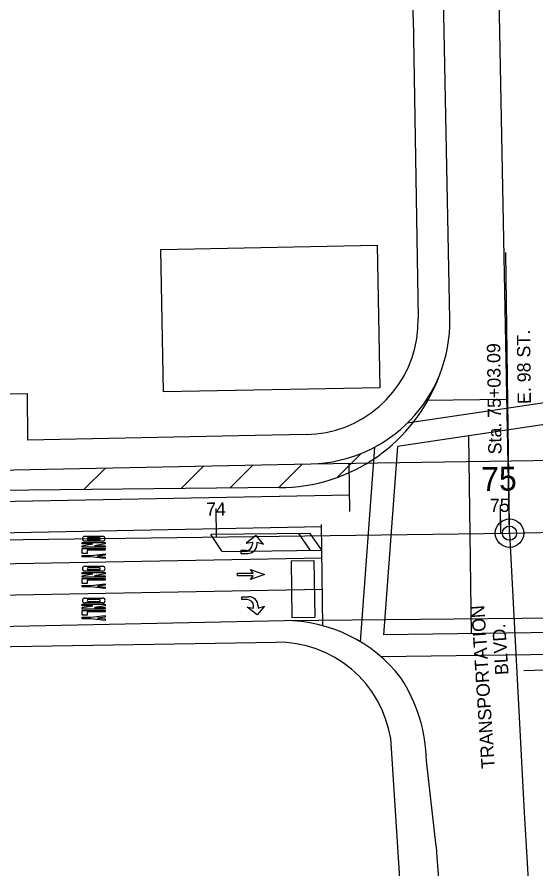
# Model space of a CAD drawing. Extents: x -2233 to 187241, y 4582 to 150524.
# Drawn here: x 107272.9 to 107455.5, y 59338.1 to 59637.9 of the extents above; entities that cross this region are included whole.
import ezdxf

# ---------------------------------------------------------------- set-up
doc = ezdxf.new("R2010")
doc.units = 0
for name, color, linetype in [('BLDG', 7, 'Continuous'), ('GE_X_CL_100', 7, 'Continuous'), ('GE_X_CL_20', 7, 'Continuous'), ('GE_X_CL_2000', 7, 'Continuous'), ('GE_X_CL_50', 7, 'Continuous'), ('PM_P_Cells', 7, 'Continuous'), ('PM_P_Channelizing_Line', 7, 'Continuous'), ('PM_P_CL_Double_Solid', 7, 'Continuous'), ('PM_P_Crosswalk', 7, 'Continuous'), ('PM_P_Dotted_Line', 7, 'Continuous'), ('PM_P_Edge_Line', 7, 'Continuous'), ('PM_P_Stop_Line', 7, 'Continuous'), ('PM_P_Text', 7, 'Continuous'), ('PM_P_Transverse_Line', 7, 'Continuous'), ('ROAD', 7, 'Continuous'), ('RW_X_Fee_RW', 7, 'Continuous'), ('SG_P_Detection', 7, 'Continuous')]:
    doc.layers.add(name, color=color, linetype=linetype)

msp = doc.modelspace()

# ---------------------------------------------------------------- linework, layer by layer
at = {"layer": 'BLDG'}
msp.add_lwpolyline([(107400.52, 59507.44), (107324.44, 59505.98), (107323.49, 59556.17), (107399.57, 59557.62)], close=True, dxfattribs=at)
at = {"layer": 'GE_X_CL_100'}
for p, q in [((107343.14, 59454.91), (107343.01, 59464.91)), ((107443.13, 59456.21), (107443, 59466.21))]:
    msp.add_line(p, q, dxfattribs=at)
msp.add_circle((107446.21, 59456.25), 5, dxfattribs=at)
at = {"layer": 'GE_X_CL_20'}
for p, q in [((107446.21, 59456.25), (107440.88, 59729.76)), ((107446.21, 59456.25), (107777.4, 59464.42)), ((106987.56, 59450.3), (107446.21, 59456.25))]:
    msp.add_line(p, q, dxfattribs=at)
at = {"layer": 'GE_X_CL_2000'}
for p, q in [((107446.21, 59456.25), (107777.4, 59464.42)), ((106987.56, 59450.3), (107446.21, 59456.25))]:
    msp.add_line(p, q, dxfattribs=at)
msp.add_lwpolyline([(107446.21, 59456.25), (107451.38, 59357.9), (107456.65, 59268.72), (107462.78, 59175.01), (107473.27, 58996.9), (107481.81, 58861.26)], dxfattribs=at)
at = {"layer": 'GE_X_CL_50'}
for p, q in [((107446.18, 59458.75), (107444.93, 59555.03)), ((107443.13, 59456.21), (107443.06, 59461.21)), ((107343.14, 59454.91), (107343.07, 59459.91))]:
    msp.add_line(p, q, dxfattribs=at)
msp.add_circle((107446.21, 59456.25), 2.5, dxfattribs=at)
at = {"layer": 'PM_P_Cells'}
for p, q in [((107296.71, 59455.15), (107297.87, 59455.15)), ((107297.87, 59455.15), (107297.87, 59454.65)), ((107297.87, 59454.65), (107297.87, 59455.15)), ((107297.87, 59455.15), (107301.87, 59455.15)), ((107301.87, 59454.65), (107297.87, 59454.65)), ((107301.87, 59454.65), (107301.87, 59455.15)), ((107301.87, 59455.15), (107303.04, 59455.15)), ((107301.87, 59455.15), (107301.87, 59454.65)), ((107357.04, 59455.44), (107353.52, 59452.77)), ((107359.6, 59452.44), (107357.04, 59455.44)), ((107295.87, 59452.48), (107295.87, 59452.98)), ((107295.87, 59452.98), (107303.87, 59452.98)), ((107295.87, 59451.81), (107299.62, 59452.48)), ((107299.62, 59452.48), (107295.87, 59452.48)), ((107295.87, 59451.31), (107295.87, 59451.81)), ((107303.04, 59453.48), (107296.71, 59453.48)), ((107297.87, 59453.98), (107301.87, 59453.98)), ((107303.87, 59452.48), (107300.12, 59451.81)), ((107300.12, 59451.81), (107303.87, 59451.81)), ((107303.87, 59452.98), (107303.87, 59452.48)), ((107303.87, 59451.81), (107303.87, 59451.31)), ((107351.6, 59452.44), (107351.6, 59452.44)), ((107353.52, 59452.77), (107355.76, 59453.1)), ((107355.76, 59453.1), (107355.76, 59452.4)), ((107357.36, 59452.44), (107357.36, 59453.1)), ((107357.36, 59453.1), (107359.6, 59452.44)), ((107359.6, 59452.44), (107359.6, 59452.44)), ((107303.87, 59451.31), (107295.87, 59451.31)), ((107295.87, 59451.23), (107295.87, 59451.23)), ((107295.87, 59449.15), (107295.87, 59450.81)), ((107295.87, 59450.81), (107303.87, 59450.81)), ((107297.54, 59449.15), (107295.87, 59449.15)), ((107303.87, 59450.31), (107297.54, 59450.31)), ((107297.54, 59450.31), (107297.54, 59449.15)), ((107298.87, 59448.4), (107303.87, 59448.98)), ((107303.87, 59451.23), (107303.87, 59451.23)), ((107303.87, 59450.81), (107303.87, 59450.31)), ((107303.87, 59448.98), (107303.87, 59448.48)), ((107353.46, 59450.1), (107351.6, 59450.1)), ((107351.6, 59450.1), (107351.6, 59449.1)), ((107351.6, 59449.1), (107354.07, 59449.1)), ((107295.87, 59447.9), (107295.87, 59448.4)), ((107295.87, 59448.4), (107298.87, 59448.4)), ((107298.87, 59447.9), (107295.87, 59447.9)), ((107303.87, 59447.31), (107298.87, 59447.9)), ((107303.87, 59448.48), (107301.21, 59448.15)), ((107301.21, 59448.15), (107303.87, 59447.81)), ((107303.87, 59447.81), (107303.87, 59447.31)), ((107296.71, 59444.6), (107297.87, 59444.6)), ((107303.04, 59442.93), (107296.71, 59442.93)), ((107297.87, 59444.6), (107297.87, 59444.1)), ((107297.87, 59444.1), (107297.87, 59444.6)), ((107297.87, 59444.6), (107301.87, 59444.6)), ((107301.87, 59444.1), (107297.87, 59444.1)), ((107297.87, 59443.43), (107301.87, 59443.43)), ((107301.87, 59444.1), (107301.87, 59444.6)), ((107301.87, 59444.6), (107303.04, 59444.6)), ((107301.87, 59444.6), (107301.87, 59444.1)), ((107356.02, 59442.22), (107355.02, 59443.46)), ((107355.02, 59443.46), (107360.02, 59441.72)), ((107295.87, 59441.93), (107295.87, 59442.43)), ((107295.87, 59442.43), (107303.87, 59442.43)), ((107295.87, 59441.26), (107299.62, 59441.93)), ((107299.62, 59441.93), (107295.87, 59441.93)), ((107295.87, 59440.76), (107295.87, 59441.26)), ((107303.87, 59440.76), (107295.87, 59440.76)), ((107295.87, 59440.68), (107295.87, 59440.68)), ((107295.87, 59438.6), (107295.87, 59440.26)), ((107295.87, 59440.26), (107303.87, 59440.26)), ((107303.87, 59439.76), (107297.54, 59439.76)), ((107297.54, 59439.76), (107297.54, 59438.6)), ((107303.87, 59441.93), (107300.12, 59441.26)), ((107300.12, 59441.26), (107303.87, 59441.26)), ((107303.87, 59442.43), (107303.87, 59441.93)), ((107303.87, 59441.26), (107303.87, 59440.76)), ((107303.87, 59440.68), (107303.87, 59440.68)), ((107303.87, 59440.26), (107303.87, 59439.76)), ((107350.52, 59441.22), (107350.52, 59442.22)), ((107350.52, 59442.22), (107356.02, 59442.22)), ((107350.52, 59441.72), (107350.52, 59441.72)), ((107356.02, 59441.22), (107350.52, 59441.22)), ((107360.02, 59441.72), (107355.02, 59439.98)), ((107355.02, 59439.98), (107356.02, 59441.22)), ((107360.02, 59441.72), (107360.02, 59441.72)), ((107297.54, 59438.6), (107295.87, 59438.6)), ((107295.87, 59437.35), (107295.87, 59437.85)), ((107295.87, 59437.85), (107298.87, 59437.85)), ((107298.87, 59437.35), (107295.87, 59437.35)), ((107298.87, 59437.85), (107303.87, 59438.43)), ((107303.87, 59436.76), (107298.87, 59437.35)), ((107303.87, 59437.93), (107301.21, 59437.6)), ((107301.21, 59437.6), (107303.87, 59437.26)), ((107303.87, 59438.43), (107303.87, 59437.93)), ((107303.87, 59437.26), (107303.87, 59436.76)), ((107351.98, 59432.87), (107351.98, 59433.87)), ((107351.98, 59433.87), (107354.46, 59433.87)), ((107295.87, 59430.72), (107295.87, 59431.22)), ((107295.87, 59431.22), (107303.87, 59431.22)), ((107295.87, 59430.06), (107299.62, 59430.72)), ((107299.62, 59430.72), (107295.87, 59430.72)), ((107296.71, 59433.39), (107297.87, 59433.39)), ((107303.04, 59431.72), (107296.71, 59431.72)), ((107297.87, 59433.39), (107297.87, 59432.89)), ((107297.87, 59432.89), (107297.87, 59433.39)), ((107297.87, 59433.39), (107301.87, 59433.39)), ((107301.87, 59432.89), (107297.87, 59432.89)), ((107297.87, 59432.22), (107301.87, 59432.22)), ((107303.87, 59430.72), (107300.12, 59430.06)), ((107301.87, 59432.89), (107301.87, 59433.39)), ((107301.87, 59433.39), (107303.04, 59433.39)), ((107301.87, 59433.39), (107301.87, 59432.89)), ((107303.87, 59431.22), (107303.87, 59430.72)), ((107353.84, 59432.87), (107351.98, 59432.87)), ((107351.98, 59430.53), (107351.98, 59430.53)), ((107356.14, 59429.87), (107356.14, 59430.57)), ((107359.98, 59430.53), (107357.42, 59427.53)), ((107357.74, 59430.53), (107357.74, 59429.87)), ((107357.74, 59429.87), (107359.98, 59430.53)), ((107359.98, 59430.53), (107359.98, 59430.53)), ((107295.87, 59429.56), (107295.87, 59430.06)), ((107303.87, 59429.56), (107295.87, 59429.56)), ((107295.87, 59429.47), (107295.87, 59429.47)), ((107295.87, 59427.39), (107295.87, 59429.06)), ((107295.87, 59429.06), (107303.87, 59429.06)), ((107303.87, 59428.56), (107297.54, 59428.56)), ((107297.54, 59428.56), (107297.54, 59427.39)), ((107300.12, 59430.06), (107303.87, 59430.06)), ((107303.87, 59430.06), (107303.87, 59429.56)), ((107303.87, 59429.47), (107303.87, 59429.47)), ((107303.87, 59429.06), (107303.87, 59428.56)), ((107357.42, 59427.53), (107353.9, 59430.2)), ((107353.9, 59430.2), (107356.14, 59429.87)), ((107297.54, 59427.39), (107295.87, 59427.39)), ((107295.87, 59426.14), (107295.87, 59426.64)), ((107295.87, 59426.64), (107298.87, 59426.64)), ((107298.87, 59426.14), (107295.87, 59426.14)), ((107298.87, 59426.64), (107303.87, 59427.22)), ((107303.87, 59425.56), (107298.87, 59426.14)), ((107303.87, 59426.72), (107301.21, 59426.39)), ((107301.21, 59426.39), (107303.87, 59426.06)), ((107303.87, 59427.22), (107303.87, 59426.72)), ((107303.87, 59426.06), (107303.87, 59425.56))]:
    msp.add_line(p, q, dxfattribs=at)
for centre, radius, start, end in [((107296.71, 59454.31), 0.833, 90, 270), ((107297.87, 59454.31), 0.333, 90, 270), ((107301.87, 59454.31), 0.333, 270, 90), ((107303.04, 59454.31), 0.833, 270, 90), ((107353.46, 59452.4), 2.3, 270, 0), ((107354.07, 59452.39), 3.28, 270, 0.9085), ((107296.71, 59443.76), 0.833, 90, 270), ((107297.87, 59443.76), 0.333, 90, 270), ((107301.87, 59443.76), 0.333, 270, 90), ((107303.04, 59443.76), 0.833, 270, 90), ((107354.46, 59430.59), 3.28, 359.0915, 90), ((107296.71, 59432.56), 0.833, 90, 270), ((107297.87, 59432.56), 0.333, 90, 270), ((107301.87, 59432.56), 0.333, 270, 90), ((107303.04, 59432.56), 0.833, 270, 90), ((107353.84, 59430.57), 2.3, 0, 90)]:
    msp.add_arc(centre, radius, start, end, dxfattribs=at)
at = {"layer": 'PM_P_Channelizing_Line'}
for p, q in [((107174.27, 59443.73), (107380.24, 59447.55)), ((107113.13, 59431.59), (107380.38, 59436.56))]:
    msp.add_line(p, q, dxfattribs=at)
at = {"layer": 'PM_P_CL_Double_Solid'}
msp.add_line((107174.12, 59454.73), (107380.09, 59458.55), dxfattribs=at)
at = {"layer": 'PM_P_Crosswalk'}
for p, q in [((107469.4, 59503.79), (107410.18, 59494.94)), ((107471.83, 59496.55), (107406.76, 59486.82)), ((107398.74, 59486.55), (107393.69, 59418.02)), ((107406.76, 59486.82), (107401.88, 59420.45)), ((107500.43, 59421.79), (107401.88, 59420.45)), ((107498.3, 59414.02), (107401.01, 59412.7))]:
    msp.add_line(p, q, dxfattribs=at)
at = {"layer": 'PM_P_Dotted_Line'}
msp.add_line((107431.77, 59490.56), (107432.67, 59420.87), dxfattribs=at)
at = {"layer": 'PM_P_Edge_Line'}
msp.add_line((107365.13, 59472.28), (106960.11, 59468.34), dxfattribs=at)
msp.add_arc((107365.13, 59532.28), 60, 270, 340.143, dxfattribs=at)
at = {"layer": 'PM_P_Stop_Line'}
for p, q in [((107416.9, 59503.06), (107445.29, 59503.48)), ((107380.55, 59423.65), (107380.08, 59459.28)), ((107451.19, 59407.95), (107493.66, 59409.16))]:
    msp.add_line(p, q, dxfattribs=at)
at = {"layer": 'PM_P_Text'}
for p, q in [((107390.02, 59463.86), (107389.8, 59480.89)), ((107173.98, 59465.73), (107389.95, 59469.74))]:
    msp.add_line(p, q, dxfattribs=at)
at = {"layer": 'PM_P_Transverse_Line'}
for p, q in [((107394, 59484.34), (107385.51, 59475.85)), ((107303.99, 59479.19), (107296.42, 59471.61)), ((107338.66, 59479.91), (107330.69, 59471.95)), ((107355.99, 59480.27), (107347.83, 59472.11)), ((107373.32, 59480.63), (107364.97, 59472.28))]:
    msp.add_line(p, q, dxfattribs=at)
at = {"layer": 'ROAD'}
for p, q in [((107425.21, 59531.65), (107421.35, 59729.38)), ((107376.26, 59480.69), (107511.44, 59482.7)), ((107112.12, 59475.2), (107376.26, 59480.69)), ((107125.33, 59420.46), (107367, 59425.49)), ((107367, 59425.49), (107530.86, 59427.16)), ((107420.4, 59346.05), (107416.98, 59376.08))]:
    msp.add_line(p, q, dxfattribs=at)
msp.add_lwpolyline([(107420.4, 59346.05), (107420.53, 59343.76), (107429.07, 59231.95), (107442.94, 59083.74), (107446.07, 59038.65), (107454.25, 58913.59), (107463.36, 58763.89), (107488.42, 58368.42), (107518.65, 57889.33), (107544.78, 57469.42), (107555.22, 57324.46)], dxfattribs=at)
for centre, radius, start, end in [((107375.22, 59530.68), 50, 271.1903, 1.1172), ((107366.83, 59373.41), 52.08, 37.7998, 89.8121), ((107361.66, 59375.06), 55.33, 1.053, 33.1626)]:
    msp.add_arc(centre, radius, start, end, dxfattribs=at)
at = {"layer": 'RW_X_Fee_RW'}
for p, q in [((107412.31, 59637.84), (107414.05, 59531.83)), ((107276.46, 59505.37), (107276.58, 59489.04)), ((107411.73, 59268.73), (107404.69, 59380.41))]:
    msp.add_line(p, q, dxfattribs=at)
for points in [[(107412.31, 59637.84), (107411.81, 59680.5), (107410.86, 59760.5)], [(107374.66, 59490.98), (107378.16, 59491.19), (107381.63, 59491.7), (107385.03, 59492.51), (107388.36, 59493.62), (107391.57, 59495.02), (107394.65, 59496.69), (107397.57, 59498.62), (107400.31, 59500.8), (107402.85, 59503.21), (107405.17, 59505.84), (107407.25, 59508.66), (107409.08, 59511.65), (107410.63, 59514.78), (107411.91, 59518.05), (107412.9, 59521.41), (107413.59, 59524.84), (107413.97, 59528.32), (107414.05, 59531.83)], [(106844.84, 59497.59), (107050.71, 59501.3), (107276.46, 59505.37)], [(107374.66, 59490.98), (107356.75, 59490.63), (107276.58, 59489.04)], [(107032.19, 59412.57), (107142.8, 59414.33), (107184.8, 59415), (107364.13, 59417.86)], [(107404.69, 59380.41), (107404.38, 59383.98), (107403.59, 59387.49), (107402.58, 59390.92), (107401.26, 59394.25), (107399.65, 59397.45), (107397.75, 59400.49), (107395.6, 59403.35), (107393.19, 59406.01), (107390.56, 59408.44), (107387.72, 59410.62), (107384.7, 59412.54), (107381.52, 59414.19), (107378.2, 59415.54), (107374.77, 59416.59), (107371.27, 59417.33), (107367.71, 59417.83), (107364.13, 59417.86)]]:
    msp.add_lwpolyline(points, dxfattribs=at)
at = {"layer": 'SG_P_Detection'}
for p, q in [((107376.05, 59456.19), (107341.05, 59455.75)), ((107345.12, 59449.8), (107341.05, 59455.75)), ((107376.12, 59450.19), (107372.05, 59456.14)), ((107380.12, 59450.24), (107376.05, 59456.19)), ((107395.22, 59456.33), (107395.22, 59456.33)), ((107345.12, 59449.8), (107380.12, 59450.24)), ((107358.3, 59449.65), (107358.3, 59449.65)), ((107369.4, 59446.54), (107377.39, 59446.69)), ((107369.4, 59446.54), (107369.65, 59426.54)), ((107377.39, 59446.69), (107377.65, 59426.69)), ((107369.65, 59426.54), (107377.65, 59426.69))]:
    msp.add_line(p, q, dxfattribs=at)

# ---------------------------------------------------------------- texts
at = {"layer": 'GE_X_CL_100'}
msp.add_text('75', height=8.4, rotation=0.7431, dxfattribs=at).set_placement((107436.31, 59471.12))
at = {"layer": 'GE_X_CL_50'}
for s, height, rotation, p in [('E. 98 ST.', 4.68, 90.7431, (107453.77, 59501.76)), ('Sta. 75+03.09', 4.68, 90.7431, (107443.41, 59484.02)), ('74', 4.68, 0.7431, (107339.43, 59462.36)), ('75', 4.68, 0.7431, (107439.32, 59463.66)), ('TRANSPORTATION', 4.6772, 93.7315, (107441.05, 59373.47)), ('BLVD.', 4.677, 93.7315, (107445.88, 59406.47))]:
    msp.add_text(s, height=height, rotation=rotation, dxfattribs=at).set_placement(p)

doc.saveas('drawing.dxf')
